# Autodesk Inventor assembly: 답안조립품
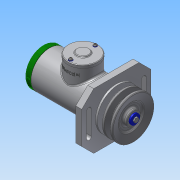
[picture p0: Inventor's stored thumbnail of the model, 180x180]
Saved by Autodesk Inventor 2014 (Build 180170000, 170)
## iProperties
Created: 2017-10
Part Number: 답안조립품
Document SubType Name: Assembly
Designer: user
Author: user
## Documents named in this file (20)
- C:\Users\user\Desktop\471008V1002\답안조립품.iam
- C:\Users\user\Desktop\471008V1002\본체.ipt
- C:\Users\user\Desktop\471008V1002\사이드 커버.ipt
- 사이드 커버.ipt
- C:\Users\user\Desktop\471008V1002\축.ipt
- C:\Users\user\Desktop\471008V1002\멈춤링 15 x 1.ipt
- C:\Users\user\Desktop\471008V1002\멈춤링 35x1.6.ipt
- C:\Users\user\Desktop\471008V1002\베어링 15 x 35 x 11.ipt
- C:\Users\user\Desktop\471008V1002\부시1.ipt
- C:\Users\user\Desktop\471008V1002\부시2.ipt
- C:\Users\user\Desktop\471008V1002\와셔 10x21.ipt
- C:\Users\user\Desktop\471008V1002\너트 M10.ipt
- C:\Users\user\Desktop\471008V1002\오일 실 15 25 7.ipt
- C:\Users\user\Desktop\471008V1002\키 4 x 4 x 18.ipt
- C:\Users\user\Desktop\471008V1002\V-벨트풀리.ipt
- C:\Users\user\Desktop\471008V1002\와셔 4x16.ipt
- C:\Users\user\Desktop\471008V1002\볼트 M4 x 10.ipt
- C:\Users\user\Desktop\471008V1002\탑 커버.ipt
- C:\Users\user\Desktop\471008V1002\와셔 3x6.ipt
- C:\Users\user\Desktop\471008V1002\십자볼트 M3 x 10.ipt
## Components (2 placed, 2 different names)
1. V-벨트풀리:1
2. ISO 4017 M4 x 10:1
